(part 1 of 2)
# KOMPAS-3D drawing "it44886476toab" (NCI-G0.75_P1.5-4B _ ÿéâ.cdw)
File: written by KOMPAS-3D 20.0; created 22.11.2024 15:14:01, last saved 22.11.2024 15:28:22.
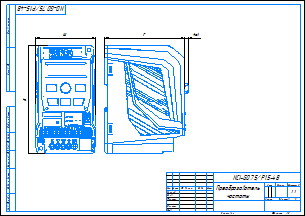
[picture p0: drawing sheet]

Sheet 1: A3, landscape

Document properties: Автор: admin

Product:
- Part/product: it44886476toab
    Масса: 2.32322
  - Body: Тело 2
      Масса: 0.00113358
  - Body: Тело 3
      Масса: 0.00113358
  - Body: Тело 4
      Масса: 0.000355433
  - Body: Тело 6
      Масса: 0.000355433
  - Body: Тело 7
      Масса: 0.000703761
  - Body: Тело 8
      Масса: 0.000703761
  - Body: Тело 10
      Масса: 0.0160396
  - Body: Тело 11
      Масса: 0.000703761
  - Body: Тело 13
      Масса: 0.000703761
  - Body: Тело 14
      Масса: 0.000703761
  - Body: Тело 18
      Масса: 0.0117014
  - Body: Тело 20
      Масса: 0.120334
  - Body: Тело 21
      Масса: 0.0864411
  - Body: Тело 22
      Масса: 0.0636504
  - Body: Тело 25
      Масса: 0.00135688
  - Body: Тело 26
      Масса: 0.00135688
  - Body: Тело 27
      Масса: 0.00135688
  - Body: Тело 30
      Масса: 0.000935996
  - Body: Тело 34
      Масса: 0.00831628
  - Body: Тело 36
      Масса: 0.0668131
  - Body: Тело 37
      Масса: 0.0343584
  - Body: Тело 39
      Масса: 0.0119524
  - Body: Тело 40
      Масса: 0.0119524
  - Body: Тело 42
      Масса: 0.0119524
  - Body: Тело 43
      Масса: 0.0119524
  - Body: Тело 46
      Масса: 0.0119034
  - Body: Тело 47
      Масса: 0.551587
  - Body: Тело 51
      Масса: 1.32696e-05
  - Body: Тело 54
      Масса: 1.32696e-05
  - Body: Тело 55
      Масса: 1.32696e-05
  - Body: Тело 56
      Масса: 1.32696e-05
  - Body: Тело 58
      Масса: 1.32696e-05
  - Body: Тело 61
      Масса: 1.32696e-05
  - Body: Тело 57
      Масса: 1.32696e-05
  - Body: Тело 63
      Масса: 1.65581e-05
  - Body: Тело 66
      Масса: 1.65581e-05
  - Body: Тело 67
      Масса: 1.65581e-05
  - Body: Тело 68
      Масса: 1.65581e-05
  - Body: Тело 69
      Масса: 1.65581e-05
  - Body: Тело 73
      Масса: 1.65581e-05
  - Body: Тело 48
      Масса: 0.00853877
  - Body: Тело 74
      Масса: 1.65581e-05
  - Body: Тело 78
      Масса: 1.65581e-05
  - Body: Тело 79
      Масса: 1.32696e-05
  - Body: Тело 80
      Масса: 1.32696e-05
  - Body: Тело 82
      Масса: 1.32696e-05
  - Body: Тело 83
      Масса: 1.32696e-05
  - Body: Тело 84
      Масса: 1.32696e-05
  - Body: Тело 87
      Масса: 0.000966482
  - Body: Тело 88
      Масса: 0.000873873
  - Body: Тело 15
      Масса: 0.000703761
  - Body: Тело 91
      Масса: 0.0246688
  - Body: Тело 92
      Масса: 3.83377e-05
  - Body: Тело 94
      Масса: 0.00554276
  - Body: Тело 96
      Масса: 0.00181049
  - Body: Тело 101
      Масса: 1.32696e-05
  - Body: Тело 90
      Масса: 0.000966482
  - Body: Тело 102
      Масса: 1.32696e-05
  - Body: Тело 104
      Масса: 1.32696e-05
  - Body: Тело 107
      Масса: 1.32696e-05
  - Body: Тело 108
      Масса: 1.32696e-05
  - Body: Тело 111
      Масса: 0.000194606
  - Body: Тело 115
      Масса: 0.000413213
  - Body: Тело 123
      Масса: 1.65581e-05
  - Body: Тело 127
      Масса: 1.32696e-05
  - Body: Тело 128
      Масса: 1.32696e-05
  - Body: Тело 129
      Масса: 1.32696e-05
  - Body: Тело 112
      Масса: 0.000413213
  - Body: Тело 130
      Масса: 1.32696e-05
  - Body: Тело 16
      Масса: 0.000703761
  - Body: Тело 131
      Масса: 1.32696e-05
  - Body: Тело 132
      Масса: 1.32696e-05
  - Body: Тело 133
      Масса: 1.32696e-05
  - Body: Тело 38
      Масса: 0.00631989
  - Body: Тело 135
      Масса: 1.32696e-05
  - Body: Тело 136
      Масса: 1.32696e-05
  - Body: Тело 142
      Масса: 0.000213463
  - Body: Тело 144
      Масса: 1.32696e-05
  - Body: Тело 62
      Масса: 1.32696e-05
  - Body: Тело 24
      Масса: 0.0110484
  - Body: Тело 147
      Масса: 1.32696e-05
  - Body: Тело 148
      Масса: 1.32696e-05
  - Body: Тело 154
      Масса: 1.32696e-05
  - Body: Тело 156
      Масса: 1.32696e-05
  - Body: Тело 158
      Масса: 1.32696e-05
  - Body: Тело 116
      Масса: 0.000413213
  - Body: Тело 159
      Масса: 1.32696e-05
  - Body: Тело 165
      Масса: 1.65581e-05
  - Body: Тело 166
      Масса: 1.32696e-05
  - Body: Тело 140
      Масса: 0.000213463
  - Body: Тело 169
      Масса: 1.32696e-05
  - Body: Тело 171
      Масса: 1.32696e-05
  - Body: Тело 153
      Масса: 1.32696e-05
  - Body: Тело 172
      Масса: 1.65581e-05
  - Body: Тело 173
      Масса: 1.32696e-05
  - Body: Тело 137
      Масса: 1.32696e-05
  - Body: Тело 45
      Масса: 0.0267013
  - Body: Тело 175
      Масса: 1.32696e-05
  - Body: Тело 177
      Масса: 1.32696e-05
  - Body: Тело 50
      Масса: 0.00101975
  - Body: Тело 44
      Масса: 0.0119524
  - Body: Тело 178
      Масса: 1.32696e-05
  - Body: Тело 179
      Масса: 1.32696e-05
  - Body: Тело 181
      Масса: 1.32696e-05
  - Body: Тело 182
      Масса: 1.32696e-05
  - Body: Тело 183
      Масса: 1.32696e-05
  - Body: Тело 188
      Масса: 1.32696e-05
  - Body: Тело 189
      Масса: 1.32696e-05
  - Body: Тело 192
      Масса: 1.32696e-05
  - Body: Тело 195
      Масса: 1.32696e-05
  - Body: Тело 197
      Масса: 1.32696e-05
  - Body: Тело 198
      Масса: 1.32696e-05
  - Body: Тело 199
      Масса: 1.32696e-05
  - Body: Тело 29
      Масса: 0.00135688
  - Body: Тело 201
      Масса: 1.32696e-05
  - Body: Тело 202
      Масса: 1.32696e-05
  - Body: Тело 205
      Масса: 1.32696e-05
  - Body: Тело 208
      Масса: 1.7366e-05
  - Body: Тело 209
      Масса: 1.32696e-05
  - Body: Тело 211
      Масса: 1.32696e-05
  - Body: Тело 212
      Масса: 1.32696e-05
  - Body: Тело 214
      Масса: 1.32696e-05
  - Body: Тело 9
      Масса: 0.000703761
  - Body: Тело 215
      Масса: 1.65581e-05
  - Body: Тело 217
      Масса: 1.32696e-05
  - Body: Тело 218
      Масса: 1.32696e-05
  - Body: Тело 219
      Масса: 1.32696e-05
  - Body: Тело 220
      Масса: 1.32696e-05
  - Body: Тело 221
      Масса: 1.65581e-05
  - Body: Тело 223
      Масса: 1.32696e-05
  - Body: Тело 162
      Масса: 1.65581e-05
  - Body: Тело 224
      Масса: 1.32696e-05
  - Body: Тело 228
      Масса: 1.32696e-05
  - Body: Тело 184
      Масса: 1.32696e-05
  - Body: Тело 230
      Масса: 1.32696e-05
  - Body: Тело 231
      Масса: 0.00398049
  - Body: Тело 232
      Масса: 5.48304e-05
  - Body: Тело 233
      Масса: 1.7366e-05
  - Body: Тело 1
      Масса: 0.00113358
  - Body: Тело 237
      Масса: 1.7366e-05
  - Body: Тело 141
      Масса: 0.000213463
  - Body: Тело 241
      Масса: 0.000424983
  - Body: Тело 65
      Масса: 1.65581e-05
  - Body: Тело 242
      Масса: 1.65581e-05
  - Body: Тело 243
      Масса: 1.65581e-05
  - Body: Тело 245
      Масса: 1.65581e-05
  - Body: Тело 234
      Масса: 1.7366e-05
  - Body: Тело 114
      Масса: 0.000413213
  - Body: Тело 19
      Масса: 0.0117014
  - Body: Тело 248
      Масса: 1.7366e-05
  - Body: Тело 249
      Масса: 1.7366e-05
  - Body: Тело 250
      Масса: 1.7366e-05
  - Body: Тело 254
      Масса: 1.32696e-05
  - Body: Тело 255
      Масса: 1.7366e-05
  - Body: Тело 119
      Масса: 0.000413213
  - Body: Тело 256
      Масса: 1.7366e-05
  - Body: Тело 167
      Масса: 1.32696e-05
  - Body: Тело 260
      Масса: 1.7366e-05
  - Body: Тело 261
      Масса: 3.83377e-05
  - Body: Тело 170
      Масса: 1.32696e-05
  - Body: Тело 463
      Масса: 0.000404362
  - Body: Тело 226
      Масса: 0.000413213
  - Body: Тело 464
      Масса: 0.00829425
  - Body: Тело 268
      Масса: 5.48304e-05
  - Body: Тело 467
      Масса: 0.00436982
  - Body: Тело 475
      Масса: 1.51773e-05
  - Body: Тело 451
      Масса: 6.34685e-05
  - Body: Тело 478
      Масса: 1.51773e-05
  - Body: Тело 465
      Масса: 0.00829114
  - Body: Тело 383
      Масса: 0.000340816
  - Body: Тело 125
      Масса: 1.65581e-05
  - Body: Тело 643
      Масса: 0.000158536
  - Body: Тело 514
      Масса: 1.51773e-05
  - Body: Тело 483
      Масса: 1.51773e-05
  - Body: Тело 486
      Масса: 0.000158536
  - Body: Тело 581
      Масса: 1.65581e-05
  - Body: Тело 490
      Масса: 1.51773e-05
  - Body: Тело 491
      Масса: 1.65581e-05
  - Body: Тело 433
      Масса: 0.000118347
  - Body: Тело 496
      Масса: 1.51773e-05
  - Body: Тело 437
      Масса: 0.00113358
  - Body: Тело 535
      Масса: 1.52051e-05
  - Body: Тело 498
      Масса: 1.51773e-05
  - Body: Тело 60
      Масса: 1.32696e-05
  - Body: Тело 369
      Масса: 1.32696e-05
  - Body: Тело 501
      Масса: 1.51773e-05
  - Body: Тело 503
      Масса: 1.51773e-05
  - Body: Тело 447
      Масса: 0.000307437
  - Body: Тело 187
      Масса: 1.32696e-05
  - Body: Тело 12
      Масса: 0.000703761
  - Body: Тело 507
      Масса: 1.51773e-05
  - Body: Тело 174
      Масса: 1.65581e-05
  - Body: Тело 587
      Масса: 1.32696e-05
  - Body: Тело 155
      Масса: 1.32696e-05
  - Body: Тело 512
      Масса: 1.51773e-05
  - Body: Тело 515
      Масса: 0.00507372
  - Body: Тело 510
      Масса: 1.51773e-05
  - Body: Тело 487
      Масса: 1.65581e-05
  - Body: Тело 432
      Масса: 0.000118347
  - Body: Тело 524
      Масса: 1.65581e-05
  - Body: Тело 637
      Масса: 1.51773e-05
  - Body: Тело 519
      Масса: 1.7366e-05
  - Body: Тело 427
      Масса: 1.32696e-05
  - Body: Тело 520
      Масса: 5.48304e-05
  - Body: Тело 326
      Масса: 1.32696e-05
  - Body: Тело 509
      Масса: 1.51773e-05
  - Body: Тело 571
      Масса: 0.00166679
  - Body: Тело 521
      Масса: 1.32696e-05
  - Body: Тело 522
      Масса: 1.65581e-05
  - Body: Тело 49
      Масса: 0.00944
  - Body: Тело 319
      Масса: 1.32696e-05
  - Body: Тело 458
      Масса: 1.51773e-05
  - Body: Тело 523
      Масса: 0.000255388
  - Body: Тело 191
      Масса: 1.32696e-05
  - Body: Тело 590
      Масса: 1.32696e-05
  - Body: Тело 599
      Масса: 7.12116e-06
  - Body: Тело 528
      Масса: 0.000141095
  - Body: Тело 64
      Масса: 1.65581e-05
  - Body: Тело 468
      Масса: 0.0253857
  - Body: Тело 216
      Масса: 0.000280294
  - Body: Тело 443
      Масса: 0.00113358
  - Body: Тело 239
      Масса: 5.48304e-05
  - Body: Тело 200
      Масса: 1.32696e-05
  - Body: Тело 579
      Масса: 0.00017125
  - Body: Тело 529
      Масса: 5.61948e-05
  - Body: Тело 493
      Масса: 1.51773e-05
  - Body: Тело 532
      Масса: 5.61948e-05
  - Body: Тело 343
      Масса: 0.00166679
  - Body: Тело 616
      Масса: 1.63919e-05
  - Body: Тело 462
      Масса: 0.000404362
  - Body: Тело 542
      Масса: 0.000158536
  - Body: Тело 543
      Масса: 0.000158536
  - Body: Тело 615
      Масса: 1.63919e-05
  - Body: Тело 149
      Масса: 1.32696e-05
  - Body: Тело 146
      Масса: 1.32696e-05
  - Body: Тело 469
      Масса: 0.0113891
  - Body: Тело 544
      Масса: 0.000158536
  - Body: Тело 295
      Масса: 1.65581e-05
  - Body: Тело 120
      Масса: 0.000413213
  - Body: Тело 352
      Масса: 2.90876e-05
  - Body: Тело 502
      Масса: 1.51773e-05
  - Body: Тело 461
      Масса: 0.000404362
  - Body: Тело 145
      Масса: 1.32696e-05
  - Body: Тело 545
      Масса: 1.51773e-05
  - Body: Тело 506
      Масса: 1.51773e-05
  - Body: Тело 71
      Масса: 1.65581e-05
  - Body: Тело 41
      Масса: 0.0119524
  - Body: Тело 547
      Масса: 0.000255388
  - Body: Тело 614
      Масса: 1.63919e-05
  - Body: Тело 257
      Масса: 1.7366e-05
  - Body: Тело 549
      Масса: 0.000255388
  - Body: Тело 204
      Масса: 1.32696e-05
  - Body: Тело 35
      Масса: 0.262997
  - Body: Тело 421
      Масса: 1.7366e-05
  - Body: Тело 258
      Масса: 1.7366e-05
  - Body: Тело 504
      Масса: 1.51773e-05
  - Body: Тело 366
      Масса: 1.7366e-05
  - Body: Тело 592
      Масса: 7.12116e-06
  - Body: Тело 32
      Масса: 0.0135217
  - Body: Тело 550
      Масса: 0.000255388
  - Body: Тело 157
      Масса: 1.32696e-05
  - Body: Тело 126
      Масса: 0.000512664
  - Body: Тело 314
      Масса: 1.7366e-05
  - Body: Тело 247
      Масса: 1.7366e-05
  - Body: Тело 23
      Масса: 0.0243258
  - Body: Тело 595
      Масса: 1.32696e-05
  - Body: Тело 534
      Масса: 1.32696e-05
  - Body: Тело 552
      Масса: 4.06595e-05
  - Body: Тело 176
      Масса: 1.32696e-05
  - Body: Тело 553
      Масса: 4.06595e-05
  - Body: Тело 28
      Масса: 0.00135688
  - Body: Тело 330
      Масса: 1.7366e-05
  - Body: Тело 190
      Масса: 1.32696e-05
  - Body: Тело 416
      Масса: 1.7366e-05
  - Body: Тело 435
      Масса: 0.00113358
  - Body: Тело 634
      Масса: 1.51773e-05
  - Body: Тело 555
      Масса: 0.00166679
  - Body: Тело 556
      Масса: 0.00166679
  - Body: Тело 602
      Масса: 5.61948e-05
  - Body: Тело 630
      Масса: 1.51773e-05
  - Body: Тело 558
      Масса: 0.00726683
  - Body: Тело 505
      Масса: 1.51773e-05
  - Body: Тело 500
      Масса: 1.51773e-05
  - Body: Тело 72
      Масса: 1.65581e-05
  - Body: Тело 279
      Масса: 1.32696e-05
  - Body: Тело 298
      Масса: 3.64495e-05
  - Body: Тело 168
      Масса: 1.32696e-05
  - Body: Тело 495
      Масса: 1.51773e-05
  - Body: Тело 336
      Масса: 3.64028e-05
  - Body: Тело 629
      Масса: 1.51773e-05
  - Body: Тело 263
      Масса: 1.7366e-05
  - Body: Тело 610
      Масса: 0.00166679
  - Body: Тело 609
      Масса: 1.7366e-05
  - Body: Тело 596
      Масса: 1.32696e-05
  - Body: Тело 538
      Масса: 1.51773e-05
  - Body: Тело 476
      Масса: 1.51773e-05
  - Body: Тело 227
      Масса: 1.32696e-05
  - Body: Тело 382
      Масса: 5.48304e-05
  - Body: Тело 470
      Масса: 0.00329329
  - Body: Тело 341
      Масса: 0.00166679
  - Body: Тело 426
      Масса: 1.32696e-05
  - Body: Тело 513
      Масса: 1.51773e-05
  - Body: Тело 236
      Масса: 1.7366e-05
  - Body: Тело 585
      Масса: 4.06595e-05
  - Body: Тело 649
      Масса: 0.00426189
  - Body: Тело 531
      Масса: 5.61948e-05
  - Body: Тело 627
      Масса: 0.000255388
  - Body: Тело 621
      Масса: 1.32696e-05
  - Body: Тело 349
      Масса: 1.7366e-05
  - Body: Тело 580
      Масса: 1.32696e-05
  - Body: Тело 631
      Масса: 1.51773e-05
  - Body: Тело 185
      Масса: 1.32696e-05
  - Body: Тело 117
      Масса: 0.000413213
  - Body: Тело 623
      Масса: 1.32696e-05
  - Body: Тело 605
      Масса: 5.61948e-05
  - Body: Тело 400
      Масса: 1.7366e-05
  - Body: Тело 139
      Масса: 0.000194606
  - Body: Тело 492
      Масса: 1.51773e-05
  - Body: Тело 612
      Масса: 0.000158536
  - Body: Тело 403
      Масса: 1.7366e-05
  - Body: Тело 460
      Масса: 3.90329e-05
  - Body: Тело 608
      Масса: 0.00166679
  - Body: Тело 635
      Масса: 1.65581e-05
  - Body: Тело 264
      Масса: 1.7366e-05
  - Body: Тело 646
      Масса: 0.000137594
  - Body: Тело 110
      Масса: 1.32696e-05
  - Body: Тело 302
      Масса: 1.65581e-05
  - Body: Тело 151
      Масса: 1.65581e-05
  - Body: Тело 497
      Масса: 1.51773e-05
  - Body: Тело 620
      Масса: 1.7366e-05
  - Body: Тело 518
      Масса: 0.00166679
  - Body: Тело 633
      Масса: 1.51773e-05
  - Body: Тело 564
      Масса: 4.06595e-05
  - Body: Тело 641
      Масса: 3.90329e-05
  - Body: Тело 494
      Масса: 1.51773e-05
  - Body: Тело 280
      Масса: 1.32696e-05
  - Body: Тело 81
      Масса: 1.32696e-05
  - Body: Тело 482
      Масса: 1.51773e-05
  - Body: Тело 594
      Масса: 1.32696e-05
  - Body: Тело 561
      Масса: 1.65581e-05
  - Body: Тело 253
      Масса: 1.7366e-05
  - Body: Тело 164
      Масса: 1.32696e-05
  - Body: Тело 525
      Масса: 0.000213463
  - Body: Тело 618
      Масса: 1.63919e-05
  - Body: Тело 642
      Масса: 3.90329e-05
  - Body: Тело 113
      Масса: 0.000413213
  - Body: Тело 546
      Масса: 0.000255388
  - Body: Тело 225
      Масса: 1.32696e-05
  - Body: Тело 138
      Масса: 2.23009e-05
  - Body: Тело 284
      Масса: 1.7366e-05
  - Body: Тело 485
      Масса: 0.000158536
  - Body: Тело 456
      Масса: 1.51773e-05
  - Body: Тело 489
      Масса: 1.51773e-05
  - Body: Тело 638
      Масса: 1.7366e-05
  - Body: Тело 563
      Масса: 4.06595e-05
  - Body: Тело 566
      Масса: 1.32696e-05
  - Body: Тело 160
      Масса: 1.32696e-05
  - Body: Тело 511
      Масса: 1.51773e-05
  - Body: Тело 541
      Масса: 0.000158536
  - Body: Тело 306
      Масса: 1.65581e-05
  - Body: Тело 356
      Масса: 1.65581e-05
  - Body: Тело 591
      Масса: 7.12116e-06
  - Body: Тело 313
      Масса: 1.7366e-05
  - Body: Тело 471
      Масса: 0.00329327
  - Body: Тело 289
      Масса: 1.7366e-05
  - Body: Тело 607
      Масса: 1.32696e-05
  - Body: Тело 603
      Масса: 5.61948e-05
  - Body: Тело 600
      Масса: 5.61948e-05
  - Body: Тело 121
      Масса: 0.000413213
  - Body: Тело 624
      Масса: 1.32696e-05
  - Body: Тело 527
      Масса: 0.000141095
  - Body: Тело 622
      Масса: 1.32696e-05
  - Body: Тело 484
      Масса: 0.000158536
  - Body: Тело 601
      Масса: 5.61948e-05
  - Body: Тело 296
      Масса: 3.6965e-05
  - Body: Тело 540
      Масса: 1.51773e-05
  - Body: Тело 210
      Масса: 1.32696e-05
  - Body: Тело 611
      Масса: 0.000158536
  - Body: Тело 161
      Масса: 1.32696e-05
  - Body: Тело 650
      Масса: 0.00426189
  - Body: Тело 604
      Масса: 5.61948e-05
  - Body: Тело 342
      Масса: 0.00166679
  - Body: Тело 251
      Масса: 1.7366e-05
  - Body: Тело 194
      Масса: 1.32696e-05
  - Body: Тело 568
      Масса: 1.32696e-05
  - Body: Тело 150
      Масса: 1.32696e-05
  - Body: Тело 640
      Масса: 1.63919e-05
  - Body: Тело 440
      Масса: 0.000355433
  - Body: Тело 499
      Масса: 1.51773e-05
  - Body: Тело 589
      Масса: 1.32696e-05
  - Body: Тело 361
      Масса: 1.32696e-05
  - Body: Тело 619
      Масса: 1.32696e-05
  - Body: Тело 405
      Масса: 1.32696e-05
  - Body: Тело 551
      Масса: 0.000255388
  - Body: Тело 598
      Масса: 7.12116e-06
  - Body: Тело 583
      Масса: 4.06595e-05
  - Body: Тело 411
      Масса: 5.48304e-05
  - Body: Тело 367
      Масса: 1.32696e-05
  - Body: Тело 488
      Масса: 1.51773e-05
  - Body: Тело 163
      Масса: 1.32696e-05
  - Body: Тело 109
      Масса: 1.32696e-05
  - Body: Тело 408
      Масса: 5.48304e-05
  - Body: Тело 593
      Масса: 1.32696e-05
  - Body: Тело 387
      Масса: 1.32696e-05
  - Body: Тело 613
      Масса: 1.63919e-05
  - Body: Тело 597
      Масса: 7.12116e-06
  - Body: Тело 118
      Масса: 0.000413213
  - Body: Тело 565
      Масса: 4.06595e-05
  - Body: Тело 632
      Масса: 1.51773e-05
  - Body: Тело 379
      Масса: 1.32696e-05
  - Body: Тело 562
      Масса: 0.000382752
  - Body: Тело 262
      Масса: 1.7366e-05
  - Body: Тело 586
      Масса: 1.32696e-05
  - Body: Тело 647
      Масса: 0.00426189
  - Body: Тело 533
      Масса: 5.61948e-05
  - Body: Тело 472
      Масса: 0.00329327
  - Body: Тело 409
      Масса: 5.48304e-05
  - Body: Тело 548
      Масса: 2.98222e-05
  - Body: Тело 474
      Масса: 1.51773e-05
  - Body: Тело 363
      Масса: 1.32696e-05
  - Body: Тело 276
      Масса: 1.7366e-05
  - Body: Тело 588
      Масса: 1.32696e-05
  - Body: Тело 70
      Масса: 1.65581e-05
  - Body: Тело 584
      Масса: 4.06595e-05
  - Body: Тело 644
      Масса: 0.000158536
  - Body: Тело 625
      Масса: 1.32696e-05
  - Body: Тело 213
      Масса: 1.32696e-05
  - Body: Тело 275
      Масса: 1.7366e-05
  - Body: Тело 320
      Масса: 1.32696e-05
  - Body: Тело 399
      Масса: 1.32696e-05
  - Body: Тело 574
      Масса: 4.06595e-05
  - Body: Тело 85
      Масса: 1.32696e-05
  - Body: Тело 576
      Масса: 1.32696e-05
  - Body: Тело 575
      Масса: 1.32696e-05
  - Body: Тело 376
      Масса: 1.32696e-05
  - Body: Тело 316
      Масса: 1.32696e-05
  - Body: Тело 449
      Масса: 0.0658364
  - Body: Тело 152
      Масса: 1.32696e-05
  - Body: Тело 559
      Масса: 1.65581e-05
  - Body: Тело 645
      Масса: 1.32696e-05
  - Body: Тело 207
      Масса: 1.32696e-05
  - Body: Тело 567
      Масса: 1.32696e-05
  - Body: Тело 572
      Масса: 1.32696e-05
  - Body: Тело 203
      Масса: 1.32696e-05
  - Body: Тело 582
      Масса: 1.65581e-05
  - Body: Тело 134
      Масса: 1.32696e-05
  - Body: Тело 626
      Масса: 1.32696e-05
  - Body: Тело 578
      Масса: 1.32696e-05
  - Body: Тело 569
      Масса: 1.32696e-05
  - Body: Тело 557
      Масса: 0.00166679
  - Body: Тело 459
      Масса: 3.90329e-05
  - Body: Тело 457
      Масса: 1.51773e-05
  - Body: Тело 539
      Масса: 1.51773e-05
  - Body: Тело 455
      Масса: 1.51773e-05
  - Body: Тело 428
      Масса: 0.146258
  - Body: Тело 454
      Масса: 0.000382752
  - Body: Тело 453
      Масса: 1.63919e-05
  - Body: Тело 417
      Масса: 1.32696e-05
  - Body: Тело 517
      Масса: 0.00106884
  - Body: Тело 418
      Масса: 1.7366e-05
  - Body: Тело 401
      Масса: 1.32696e-05
  - Body: Тело 53
      Масса: 1.32696e-05
  - Body: Тело 452
      Масса: 1.63919e-05
  - Body: Тело 315
      Масса: 1.7366e-05
  - Body: Тело 222
      Масса: 1.32696e-05
  - Body: Тело 450
      Масса: 6.34685e-05
  - Body: Тело 481
      Масса: 1.51773e-05
  - Body: Тело 448
      Масса: 0.000307437
  - Body: Тело 193
      Масса: 1.32696e-05
  - Body: Тело 392
      Масса: 1.32696e-05
  - Body: Тело 577
      Масса: 1.7366e-05
  - Body: Тело 508
      Масса: 1.51773e-05
  - Body: Тело 106
      Масса: 1.32696e-05
  - Body: Тело 438
      Масса: 0.000355433
  - Body: Тело 445
      Масса: 0.00113358
  - Body: Тело 246
      Масса: 1.65581e-05
  - Body: Тело 444
      Масса: 0.000355433
  - Body: Тело 554
      Масса: 4.06595e-05
  - Body: Тело 442
      Масса: 0.000355433
  - Body: Тело 441
      Масса: 0.00113358
  - Body: Тело 323
      Масса: 1.32696e-05
  - Body: Тело 606
      Масса: 0.000137594
  - Body: Тело 439
      Масса: 0.00113358
  - Body: Тело 436
      Масса: 0.000355433
  - Body: Тело 344
      Масса: 1.32696e-05
  - Body: Тело 124
      Масса: 1.65581e-05
  - Body: Тело 5
      Масса: 0.000355433
  - Body: Тело 434
      Масса: 0.000355433
  - Body: Тело 329
      Масса: 1.32696e-05
  - Body: Тело 364
      Масса: 1.32696e-05
  - Body: Тело 431
      Масса: 0.146258
  - Body: Тело 345
      Масса: 1.32696e-05
  - Body: Тело 350
      Масса: 1.7366e-05
  - Body: Тело 430
      Масса: 0.146258
  - Body: Тело 334
      Масса: 1.7366e-05
  - Body: Тело 429
      Масса: 0.146258
  - Body: Тело 206
      Масса: 1.32696e-05
  - Body: Тело 271
      Масса: 1.32696e-05
  - Body: Тело 365
      Масса: 1.32696e-05
  - Body: Тело 425
      Масса: 1.32696e-05
  - Body: Тело 305
      Масса: 1.65581e-05
  - Body: Тело 98
      Масса: 1.65581e-05
  - Body: Тело 424
      Масса: 1.7366e-05
  - Body: Тело 423
      Масса: 1.32696e-05
  - Body: Тело 381
      Масса: 1.7366e-05
  - Body: Тело 422
      Масса: 5.48304e-05
  - Body: Тело 186
      Масса: 1.32696e-05
  - Body: Тело 420
      Масса: 1.7366e-05
  - Body: Тело 648
      Масса: 0.00426189
  - Body: Тело 419
      Масса: 1.32696e-05
  - Body: Тело 235
      Масса: 1.7366e-05
  - Body: Тело 415
      Масса: 1.7366e-05
  - Body: Тело 537
      Масса: 0.000158536
  - Body: Тело 414
      Масса: 1.32696e-05
  - Body: Тело 413
      Масса: 1.32696e-05
  - Body: Тело 412
      Масса: 1.7366e-05
  - Body: Тело 636
      Масса: 1.65581e-05
  - Body: Тело 410
      Масса: 5.48304e-05
  - Body: Тело 97
      Масса: 0.0015961
  - Body: Тело 407
      Масса: 5.48304e-05
  - Body: Тело 52
      Масса: 1.32696e-05
  - Body: Тело 393
      Масса: 1.32696e-05
  - Body: Тело 406
      Масса: 1.65581e-05
  - Body: Тело 89
      Масса: 0.00142218
  - Body: Тело 404
      Масса: 1.32696e-05
  - Body: Тело 339
      Масса: 1.32696e-05
  - Body: Тело 59
      Масса: 1.32696e-05
  - Body: Тело 402
      Масса: 1.7366e-05
  - Body: Тело 479
      Масса: 1.51773e-05
  - Body: Тело 398
      Масса: 1.65581e-05
  - Body: Тело 397
      Масса: 1.32696e-05
  - Body: Тело 396
      Масса: 1.7366e-05
  - Body: Тело 354
      Масса: 0.000213463
  - Body: Тело 395
      Масса: 1.32696e-05
  - Body: Тело 394
      Масса: 1.32696e-05
  - Body: Тело 143
      Масса: 1.32696e-05
  - Body: Тело 390
      Масса: 1.65581e-05
  - Body: Тело 93
      Масса: 3.83377e-05
  - Body: Тело 389
      Масса: 1.65581e-05
  - Body: Тело 388
      Масса: 1.32696e-05
  - Body: Тело 229
      Масса: 1.32696e-05
  - Body: Тело 386
      Масса: 1.32696e-05
  - Body: Тело 291
      Масса: 0.000213463
  - Body: Тело 385
      Масса: 1.32696e-05
  - Body: Тело 639
      Масса: 1.63919e-05
  - Body: Тело 380
      Масса: 1.32696e-05
  - Body: Тело 322
      Масса: 1.32696e-05
  - Body: Тело 372
      Масса: 1.7366e-05
  - Body: Тело 95
      Масса: 0.000935996
  - Body: Тело 378
      Масса: 0.000413213
  - Body: Тело 259
      Масса: 1.7366e-05
  - Body: Тело 76
      Масса: 1.65581e-05
  - Body: Тело 351
      Масса: 2.90876e-05
  - Body: Тело 375
      Масса: 1.32696e-05
  - Body: Тело 373
      Масса: 1.32696e-05
  - Body: Тело 75
      Масса: 1.32696e-05
  - Body: Тело 371
      Масса: 1.7366e-05
  - Body: Тело 628
      Масса: 1.51773e-05
  - Body: Тело 333
      Масса: 1.32696e-05
  - Body: Тело 370
      Масса: 1.32696e-05
  - Body: Тело 368
      Масса: 1.32696e-05
  - Body: Тело 310
      Масса: 1.7366e-05
  - Body: Тело 86
      Масса: 1.32696e-05
  - Body: Тело 286
      Масса: 1.7366e-05
  - Body: Тело 359
      Масса: 1.7366e-05
  - Body: Тело 358
      Масса: 5.48304e-05
  - Body: Тело 466
      Масса: 0.00829114
  - Body: Тело 355
      Масса: 5.48304e-05
  - Body: Тело 353
      Масса: 1.7366e-05
  - Body: Тело 362
      Масса: 1.32696e-05
  - Body: Тело 281
      Масса: 1.32696e-05
  - Body: Тело 335
      Масса: 1.32696e-05
  - Body: Тело 346
      Масса: 1.32696e-05
  - Body: Тело 357
      Масса: 1.65581e-05
  - Body: Тело 196
      Масса: 1.32696e-05
  - Body: Тело 340
      Масса: 1.32696e-05
  - Body: Тело 570
      Масса: 4.06595e-05
  - Body: Тело 338
      Масса: 1.7366e-05
  - Body: Тело 337
      Масса: 1.7366e-05
  - Body: Тело 446
      Масса: 0.000307437
  - Body: Тело 332
      Масса: 1.7366e-05
  - Body: Тело 331
      Масса: 1.7366e-05
  - Body: Тело 301
      Масса: 1.65581e-05
  - Body: Тело 328
      Масса: 1.7366e-05
  - Body: Тело 105
      Масса: 1.32696e-05
  - Body: Тело 100
      Масса: 1.65581e-05
  - Body: Тело 31
      Масса: 0.0078835
  - Body: Тело 327
      Масса: 1.32696e-05
  - Body: Тело 617
      Масса: 1.63919e-05
  - Body: Тело 99
      Масса: 1.65581e-05
  - Body: Тело 325
      Масса: 1.32696e-05
  - Body: Тело 293
      Масса: 5.48304e-05
  - Body: Тело 288
      Масса: 1.7366e-05
  - Body: Тело 480
      Масса: 1.51773e-05
  - Body: Тело 324
      Масса: 1.32696e-05
  - Body: Тело 321
      Масса: 1.32696e-05
  - Body: Тело 318
      Масса: 1.32696e-05
  - Body: Тело 317
      Масса: 1.32696e-05
  - Body: Тело 312
      Масса: 5.48304e-05
  - Body: Тело 560
      Масса: 1.65581e-05
  - Body: Тело 122
      Масса: 1.65581e-05
  - Body: Тело 311
      Масса: 5.48304e-05
  - Body: Тело 473
      Масса: 0.00425494
  - Body: Тело 309
      Масса: 1.32696e-05
  - Body: Тело 240
      Масса: 1.7366e-05
  - Body: Тело 180
      Масса: 1.32696e-05
  - Body: Тело 308
      Масса: 0.000413213
  - Body: Тело 307
      Масса: 0.000213463
  - Body: Тело 304
      Масса: 1.65581e-05
  - Body: Тело 347
      Масса: 1.32696e-05
  - Body: Тело 360
      Масса: 1.32696e-05
  - Body: Тело 384
      Масса: 5.48304e-05
  - Body: Тело 516
      Масса: 0.00507377
  - Body: Тело 303
      Масса: 1.65581e-05
  - Body: Тело 300
      Масса: 1.65581e-05
  - Body: Тело 283
      Масса: 1.7366e-05
  - Body: Тело 299
      Масса: 3.64028e-05
  - Body: Тело 297
      Масса: 3.64631e-05
  - Body: Тело 294
      Масса: 0.000413213
  - Body: Тело 252
      Масса: 5.48304e-05
  - Body: Тело 33
      Масса: 0.00516019
  - Body: Тело 292
      Масса: 1.7366e-05
  - Body: Тело 269
      Масса: 5.48304e-05
  - Body: Тело 290
      Масса: 0.000413213
  - Body: Тело 287
      Масса: 1.32696e-05
  - Body: Тело 285
      Масса: 5.48304e-05
  - Body: Тело 391
      Масса: 1.32696e-05
  - Body: Тело 526
      Масса: 5.61948e-05
  - Body: Тело 477
      Масса: 1.51773e-05
  - Body: Тело 282
      Масса: 1.7366e-05
  - Body: Тело 278
      Масса: 1.7366e-05
  - Body: Тело 530
      Масса: 5.61948e-05
  - Body: Тело 277
      Масса: 1.7366e-05
  - Body: Тело 274
      Масса: 1.7366e-05
  - Body: Тело 238
      Масса: 1.7366e-05
  - Body: Тело 273
      Масса: 5.48304e-05
  - Body: Тело 272
      Масса: 1.7366e-05
  - Body: Тело 377
      Масса: 1.65581e-05
  - Body: Тело 536
      Масса: 0.000158536
  - Body: Тело 244
      Масса: 1.65581e-05
  - Body: Тело 77
      Масса: 1.32696e-05
  - Body: Тело 270
      Масса: 1.7366e-05
  - Body: Тело 348
      Масса: 1.32696e-05
  - Body: Тело 573
      Масса: 4.06595e-05
  - Body: Тело 103
      Масса: 1.32696e-05
  - Body: Тело 267
      Масса: 1.7366e-05
  - Body: Тело 266
      Масса: 1.7366e-05
  - Body: Тело 265
      Масса: 1.32696e-05
  - Body: Тело 374
      Масса: 5.48304e-05
  - Body: Тело 17
      Масса: 0.0117014

Title block, sheet 1: Наименование: Преобразователь / частоты; designation: NCI-G0.75/P1.5-4B; Количество листов документа: 1; Форматы листов документа: A3; stored path: P:\INSTART\Технический отдел\ОР\Прочие задачи\КД на номенклатурный ряд\КД на типоразмеры ПЧ\NCI\NCI-G0.75_P1.5-4B _ ШВГ.cdw

Referenced files in P:\INSTART\Технический отдел\ОР\Уралов\Проверка КД\: KD600M-4T2R2-20240807.m3d
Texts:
  Кривая без истории:10000
  Кривая без истории:10001
  Кривая без истории:10002
  Кривая без истории:10003
  Кривая без истории:10004
  Кривая без истории:10005
  Кривая без истории:10006
  Кривая без истории:10007
  Кривая без истории:10008
  Кривая без истории:10009
  Кривая без истории:10010
  Кривая без истории:10011
  Кривая без истории:10012
  Кривая без истории:10013
  Кривая без истории:10014
  Кривая без истории:10015
  Кривая без истории:10016
  Кривая без истории:10017
  Кривая без истории:10018
  Кривая без истории:10019
  Кривая без истории:10020
  Кривая без истории:10021
  Кривая без истории:10022
  Кривая без истории:10023
  Кривая без истории:10024
  Кривая без истории:10025
  Кривая без истории:10026
  Кривая без истории:10027
  Кривая без истории:10028
  Кривая без истории:10029
  Кривая без истории:10030
  Кривая без истории:10031
  Кривая без истории:10032
  Кривая без истории:10033
  Кривая без истории:10034
  Кривая без истории:10035
  Кривая без истории:10036
  Кривая без истории:10037
  Кривая без истории:10038
  Кривая без истории:10039
  Кривая без истории:10040
  Кривая без истории:10041
  Кривая без истории:10042
  Кривая без истории:10043
  Кривая без истории:10044
  Кривая без истории:10045
  Кривая без истории:10046
  Кривая без истории:10047
  Кривая без истории:10048
  Кривая без истории:10049
  Кривая без истории:10050
  Кривая без истории:10051
  Кривая без истории:10052
  Кривая без истории:10053
  Кривая без истории:10054
  Кривая без истории:10055
  Кривая без истории:10056
  Кривая без истории:10057
  Кривая без истории:10058
  Кривая без истории:10059
  Кривая без истории:10060
  Кривая без истории:10061
  Кривая без истории:10062
  Кривая без истории:10063
  Кривая без истории:10064
  Кривая без истории:10065
  Кривая без истории:10066
  Кривая без истории:10067
  Кривая без истории:10068
  Кривая без истории:10069
  Кривая без истории:10070
  Кривая без истории:10071
  Кривая без истории:10072
  Кривая без истории:10073
  Кривая без истории:10074
  Кривая без истории:10075
  Кривая без истории:10076
  Кривая без истории:10077
  Кривая без истории:10078
  Кривая без истории:10079
  Кривая без истории:10080
  Кривая без истории:10081
  Кривая без истории:10082
  Кривая без истории:10083
  Кривая без истории:10084
  Кривая без истории:10085
  Кривая без истории:10086
  Кривая без истории:10087
  Кривая без истории:10088
  Кривая без истории:10089
  Кривая без истории:10090
  Кривая без истории:10091
  Кривая без истории:10092
  Кривая без истории:10093
  Кривая без истории:10094
  Кривая без истории:10095
  Кривая без истории:10096
  Кривая без истории:10097
  Кривая без истории:10098
  Кривая без истории:10099
  Кривая без истории:10100
  Кривая без истории:10101
  Кривая без истории:10102
  Кривая без истории:10103
  Кривая без истории:10104
  Кривая без истории:10105
  Кривая без истории:10106
  Кривая без истории:10107
  Кривая без истории:10108
  Кривая без истории:10109
  Кривая без истории:10110
  Кривая без истории:10111
  Кривая без истории:10112
  Кривая без истории:10113
  Кривая без истории:10114
  Кривая без истории:10115
  Кривая без истории:10116
  Кривая без истории:10117
  Кривая без истории:10118
  Кривая без истории:10119
  Кривая без истории:10120
  Кривая без истории:10121
  Кривая без истории:10122
  Кривая без истории:10123
  Кривая без истории:10124
  Кривая без истории:10125
  Кривая без истории:10126
  Кривая без истории:10127
  Кривая без истории:10128
  Кривая без истории:10129
  Кривая без истории:10130
  Кривая без истории:10131
  Кривая без истории:10132
  Кривая без истории:10133
  Кривая без истории:10134
  Кривая без истории:10135
  Кривая без истории:10136
  Кривая без истории:10137
  Кривая без истории:10138
  Кривая без истории:10139
  Кривая без истории:10140
  Кривая без истории:10141
  Кривая без истории:10142
  Кривая без истории:10143
  Кривая без истории:10144
  Кривая без истории:10145
  Кривая без истории:10146
  Кривая без истории:10147
  Кривая без истории:10148
  Кривая без истории:10149
  Кривая без истории:10150
  Кривая без истории:10151
  Кривая без истории:10152
  Кривая без истории:10153
  Кривая без истории:10154
  Кривая без истории:10155
  Кривая без истории:10156
  Кривая без истории:10157
  Кривая без истории:10158
  Кривая без истории:10159
  Кривая без истории:10160
  Кривая без истории:10161
  Кривая без истории:10162
  Кривая без истории:10163
  Кривая без истории:10164
  Кривая без истории:10165
  Кривая без истории:10166
  Кривая без истории:10167
  Кривая без истории:10168
  Кривая без истории:10169
  Кривая без истории:10170
  Кривая без истории:10171
  Кривая без истории:10172
  Кривая без истории:10173
  Кривая без истории:10174
  Кривая без истории:10175
  Кривая без истории:10176
  Кривая без истории:10177
  Кривая без истории:10178
  Кривая без истории:10179
  Кривая без истории:10180
  Кривая без истории:10181
  Кривая без истории:10182
  Кривая без истории:10183
  Кривая без истории:10184
  Кривая без истории:10185
  Кривая без истории:10186
  Кривая без истории:10187
  Кривая без истории:10188
  Кривая без истории:10189
  Кривая без истории:10190
  Кривая без истории:10191
  Кривая без истории:10192
  Кривая без истории:10193
  Кривая без истории:10194
  Кривая без истории:10195
  Кривая без истории:10196
  Кривая без истории:10197
  Кривая без истории:10198
  Кривая без истории:10199
  Кривая без истории:10200
  Кривая без истории:10201
  Кривая без истории:10202
  Кривая без истории:10203
  Кривая без истории:10204
  Кривая без истории:10205
  Кривая без истории:10206
  Кривая без истории:10207
  Кривая без истории:10208
  Кривая без истории:10209
  Кривая без истории:10210
  Кривая без истории:10211
  Кривая без истории:10212
  Кривая без истории:10213
  Кривая без истории:10214
  Кривая без истории:10215
  Кривая без истории:10216
  Кривая без истории:10217
  Кривая без истории:10218
  Кривая без истории:10219
  Кривая без истории:10220
  Кривая без истории:10221
  Кривая без истории:10222
  Кривая без истории:10223
  Кривая без истории:10224
  Кривая без истории:10225
  Кривая без истории:10226
  Кривая без истории:10227
  Кривая без истории:10228
  Кривая без истории:10229
  Кривая без истории:10230
  Кривая без истории:10231
  Кривая без истории:10232
  Кривая без истории:10233
  Кривая без истории:10234
  Кривая без истории:10235
  Кривая без истории:10236
  Кривая без истории:10237
  Кривая без истории:10238
  Кривая без истории:10239
  Кривая без истории:10240
  Кривая без истории:10241
  Кривая без истории:10242
  Кривая без истории:10243
  Кривая без истории:10244
  Кривая без истории:10245
  Кривая без истории:10246
  Кривая без истории:10247
  Кривая без истории:10248
  Кривая без истории:10249
  Кривая без истории:10250
  Кривая без истории:10251
  Кривая без истории:10252
  Кривая без истории:10253
  Кривая без истории:10254
  Кривая без истории:10255
  Кривая без истории:10256
  Кривая без истории:10257
  Кривая без истории:10258
  Кривая без истории:10259
  Кривая без истории:10260
  Кривая без истории:10261
  Кривая без истории:10262
  Кривая без истории:10263
  Кривая без истории:10264
  Кривая без истории:10265
  Кривая без истории:10266
  Кривая без истории:10267
  Кривая без истории:10268
  Кривая без истории:10269
  Кривая без истории:10270
  Кривая без истории:10271
  Кривая без истории:10272
  Кривая без истории:10273
  Кривая без истории:10274
  Кривая без истории:10275
  Кривая без истории:10276
  Кривая без истории:10277
  Кривая без истории:10278
  Кривая без истории:10279
  Кривая без истории:10280
  Кривая без истории:10281
  Кривая без истории:10282
  Кривая без истории:10283
  Кривая без истории:10284
  Кривая без истории:10285
  Кривая без истории:10286
  Кривая без истории:10287
  Кривая без истории:10288
  Кривая без истории:10289
  Кривая без истории:10290
  Кривая без истории:10291
  Кривая без истории:10292
  Кривая без истории:10293
  Кривая без истории:10294
  Кривая без истории:10295
  Кривая без истории:10296
  Кривая без истории:10297
  Кривая без истории:10298
  Кривая без истории:10299
  Кривая без истории:10300
  Кривая без истории:10301
  Кривая без истории:10302
  Кривая без истории:10303
  Кривая без истории:10304
  Кривая без истории:10305
  Кривая без истории:10306
  Кривая без истории:10307
  Кривая без истории:10308
  Кривая без истории:10309
  Кривая без истории:10310
  Кривая без истории:10311
  Кривая без истории:10312
  Кривая без истории:10313
  Кривая без истории:10314
  Кривая без истории:10315
  Кривая без истории:10316
  Кривая без истории:10317
  Кривая без истории:10318
  Кривая без истории:10319
  Кривая без истории:10320
  Кривая без истории:10321
  Кривая без истории:10322
  Кривая без истории:10323
  Кривая без истории:10324
  Кривая без истории:10325
  Кривая без истории:10326
  Кривая без истории:10327
  Кривая без истории:10328
  Кривая без истории:10329
  Кривая без истории:10330
  Кривая без истории:10331
  Кривая без истории:10332
  Кривая без истории:10333
  Кривая без истории:10334
  Кривая без истории:10335
  Кривая без истории:10336
  Кривая без истории:10337
  Кривая без истории:10338
  Кривая без истории:10339
  Кривая без истории:10340
  Кривая без истории:10341
  Кривая без истории:10342
  Кривая без истории:10343
  Кривая без истории:10344
  Кривая без истории:10345
  Кривая без истории:10346
  Кривая без истории:10347
  Кривая без истории:10348
  Кривая без истории:10349
  Кривая без истории:10350
  Кривая без истории:10351
  Кривая без истории:10352
  Кривая без истории:10353
  Кривая без истории:10354
  Кривая без истории:10355
  Кривая без истории:10356
  Кривая без истории:10357
  Кривая без истории:10358
  Кривая без истории:10359
  Кривая без истории:10360
  Кривая без истории:10361
  Кривая без истории:10362
  Кривая без истории:10363
  Кривая без истории:10364
  Кривая без истории:10365
  Кривая без истории:10366
  Кривая без истории:10367
  Кривая без истории:10368
  Кривая без истории:10369
  Кривая без истории:10370
  Кривая без истории:10371
  Кривая без истории:10372
  Кривая без истории:10373
  Кривая без истории:10374
  Кривая без истории:10375
  Кривая без истории:10376
  Кривая без истории:10377
  Кривая без истории:10378
  Кривая без истории:10379
  Кривая без истории:10380
  Кривая без истории:10381
  Кривая без истории:10382
  Кривая без истории:10383
  Кривая без истории:10384
  Кривая без истории:10385
  Кривая без истории:10386
  Кривая без истории:10387
  Кривая без истории:10388
  Кривая без истории:10389
  Кривая без истории:10390
  Кривая без истории:10391
  Кривая без истории:10392
  Кривая без истории:10393
  Кривая без истории:10394
  Кривая без истории:10395
  Кривая без истории:10396
  Кривая без истории:10397
  Кривая без истории:10398
  Кривая без истории:10399
  Кривая без истории:10400
  Кривая без истории:10401
  Кривая без истории:10402
  Кривая без истории:10403
  Кривая без истории:10404
  Кривая без истории:10405
  Кривая без истории:10406
  Кривая без истории:10407
  Кривая без истории:10408
  Кривая без истории:10409
  Кривая без истории:10410
  Кривая без истории:10411
  Кривая без истории:10412
  Кривая без истории:10413
  Кривая без истории:10414
  Кривая без истории:10415
  Кривая без истории:10416
  Кривая без истории:10417
  Кривая без истории:10418
  Кривая без истории:10419
  Кривая без истории:10420
  Кривая без истории:10421
  Кривая без истории:10422
  Кривая без истории:10423
  Кривая без истории:10424
  Кривая без истории:10425
  Кривая без истории:10426
  Кривая без истории:10427
  Кривая без истории:10428
  Кривая без истории:10429
  Кривая без истории:10430
  Кривая без истории:10431
  Кривая без истории:10432
  Кривая без истории:10433
  Кривая без истории:10434
  Кривая без истории:10435
  Кривая без истории:10436
  Кривая без истории:10437
  Кривая без истории:10438
  Кривая без истории:10439
  Кривая без истории:10440
  Кривая без истории:10441
  Кривая без истории:10442
  Кривая без истории:10443
  Кривая без истории:10444
  Кривая без истории:10445
  Кривая без истории:10446
  Кривая без истории:10447
  Кривая без истории:10448
  Кривая без истории:10449
  Кривая без истории:10450
  Кривая без истории:10451
  Кривая без истории:10452
  Кривая без истории:10453
  Кривая без истории:10454
  Кривая без истории:10455
  Кривая без истории:10456
  Кривая без истории:10457
  Кривая без истории:10458
  Кривая без истории:10459
  Кривая без истории:10460
  Кривая без истории:10461
  Кривая без истории:10462
  Кривая без истории:10463
  Кривая без истории:10464
  Кривая без истории:10465
  Кривая без истории:10466
  Кривая без истории:10467
  Кривая без истории:10468
  Кривая без истории:10469
  Кривая без истории:10470
  Кривая без истории:10471
  Кривая без истории:10472
  Кривая без истории:10473
  Кривая без истории:10474
  Кривая без истории:10475
  Кривая без истории:10476
  Кривая без истории:10477
  Кривая без истории:10478
  Кривая без истории:10479
  Кривая без истории:10480
  Кривая без истории:10481
  Кривая без истории:10482
  Кривая без истории:10483
  Кривая без истории:10484
  Кривая без истории:10485
  Кривая без истории:10486
  Кривая без истории:10487
  Кривая без истории:10488
  Кривая без истории:10489
  Кривая без истории:10490
  Кривая без истории:10491
  Кривая без истории:10492
  Кривая без истории:10493
  Кривая без истории:10494
  Кривая без истории:10495
  Кривая без истории:10496
  Кривая без истории:10497
  Кривая без истории:10498
  Кривая без истории:10499
  Кривая без истории:10500
  Кривая без истории:10501
  Кривая без истории:10502
  Кривая без истории:10503
  Кривая без истории:10504
  Кривая без истории:10505
  Кривая без истории:10506
  Кривая без истории:10507
  Кривая без истории:10508
  Кривая без истории:10509
  Кривая без истории:10510
  Кривая без истории:10511
  Кривая без истории:10512
  Кривая без истории:10513
  Кривая без истории:10514
  Кривая без истории:10515
  Кривая без истории:10516
  Кривая без истории:10517
  Кривая без истории:10518
  Кривая без истории:10519
  Кривая без истории:10520
  Кривая без истории:10521
  Кривая без истории:10522
  Кривая без истории:10523
  Кривая без истории:10524
  Кривая без истории:10525
  Кривая без истории:10526
  Кривая без истории:10527
  Кривая без истории:10528
  Кривая без истории:10529
  Кривая без истории:10530
  Кривая без истории:10531
  Кривая без истории:10532
  Кривая без истории:10533
  Кривая без истории:10534
  Кривая без истории:10535
  Кривая без истории:10536
  Кривая без истории:10537
  Кривая без истории:10538
  Кривая без истории:10539
  Кривая без истории:10540
  Кривая без истории:10541
  Кривая без истории:10542
  Кривая без истории:10543
  Кривая без истории:10544
  Кривая без истории:10545
  Кривая без истории:10546
  Кривая без истории:10547
  Кривая без истории:10548
  Кривая без истории:10549
  Кривая без истории:10550
  Кривая без истории:10551
  Кривая без истории:10552
  Кривая без истории:10553
  Кривая без истории:10554
  Кривая без истории:10555
  Кривая без истории:10556
  Кривая без истории:10557
  Кривая без истории:10558
  Кривая без истории:10559
  Кривая без истории:10560
  Кривая без истории:10561
  Кривая без истории:10562
  Кривая без истории:10563
  Кривая без истории:10564
  Кривая без истории:10565
  Кривая без истории:10566
  Кривая без истории:10567
  Кривая без истории:10568
  Кривая без истории:10569
  Кривая без истории:10570
  Кривая без истории:10571
  Кривая без истории:10572
  Кривая без истории:10573
  Кривая без истории:10574
  Кривая без истории:10575
  Кривая без истории:10576
  Кривая без истории:10577
  Кривая без истории:10578
  Кривая без истории:10579
  Кривая без истории:10580
  Кривая без истории:10581
  Кривая без истории:10582
  Кривая без истории:10583
  Кривая без истории:10584
  Кривая без истории:10585
  Кривая без истории:10586
  Кривая без истории:10587
  Кривая без истории:10588
  Кривая без истории:10589
  Кривая без истории:10590
  Кривая без истории:10591
  Кривая без истории:10592
  Кривая без истории:10593
  Кривая без истории:10594
  Кривая без истории:10595
  Кривая без истории:10596
  Кривая без истории:10597
  Кривая без истории:10598
  Кривая без истории:10599
  Кривая без истории:10600
  Кривая без истории:10601
  Кривая без истории:10602
  Кривая без истории:10603
  Кривая без истории:10604
  Кривая без истории:10605
  Кривая без истории:10606
  Кривая без истории:10607
  Кривая без истории:10608
  Кривая без истории:10609
  Кривая без истории:10610
  Кривая без истории:10611
  Кривая без истории:10612
  Кривая без истории:10613
  Кривая без истории:10614
  Кривая без истории:10615
  Кривая без истории:10616
  Кривая без истории:10617
  Кривая без истории:10618
  Кривая без истории:10619
  Кривая без истории:10620
  Кривая без истории:10621
  Кривая без истории:10622
  Кривая без истории:10623
  Кривая без истории:10624
  Кривая без истории:10625
  Кривая без истории:10626
  Кривая без истории:10627
  Кривая без истории:10628
  Кривая без истории:10629
  Кривая без истории:10630
  Кривая без истории:10631
  Кривая без истории:10632
  Кривая без истории:10633
  Кривая без истории:10634
  Кривая без истории:10635
  Кривая без истории:10636
  Кривая без истории:10637
  Кривая без истории:10638
  Кривая без истории:10639
  Кривая без истории:10640
  Кривая без истории:10641
  Кривая без истории:10642
  Кривая без истории:10643
  Кривая без истории:10644
  Кривая без истории:10645
  Кривая без истории:10646
  Кривая без истории:10647
  Кривая без истории:10648
  Кривая без истории:10649
  Кривая без истории:10650
  Кривая без истории:10651
  Кривая без истории:10652
  Кривая без истории:10653
  Кривая без истории:10654
  Кривая без истории:10655
  Кривая без истории:10656
  Кривая без истории:10657
  Кривая без истории:10658
  Кривая без истории:10659
  Кривая без истории:10660
  Кривая без истории:10661
  Кривая без истории:10662
  Кривая без истории:10663
  Кривая без истории:10664
  Кривая без истории:10665
  Кривая без истории:10666
  Кривая без истории:10667
  Кривая без истории:10668
  Кривая без истории:10669
  Кривая без истории:10670
  Кривая без истории:10671
  Кривая без истории:10672
  Кривая без истории:10673
  Кривая без истории:10674
  Кривая без истории:10675
  Кривая без истории:10676
  Кривая без истории:10677
  Кривая без истории:10678
  Кривая без истории:10679
  Кривая без истории:10680
  Кривая без истории:10681
  Кривая без истории:10682
  Кривая без истории:10683
  Кривая без истории:10684
  Кривая без истории:10685
  Кривая без истории:10686
  Кривая без истории:10687
  Кривая без истории:10688
  Кривая без истории:10689
  Кривая без истории:10690
  Кривая без истории:10691
  Кривая без истории:10692
  Кривая без истории:10693
  Кривая без истории:10694
  Кривая без истории:10695
  Кривая без истории:10696
  Кривая без истории:10697
  Кривая без истории:10698
  Кривая без истории:10699
  Кривая без истории:10700
  Кривая без истории:10701
  Кривая без истории:10702
  Кривая без истории:10703
  Кривая без истории:10704
  Кривая без истории:10705
  Кривая без истории:10706
  Кривая без истории:10707
  Кривая без истории:10708
  Кривая без истории:10709
  Кривая без истории:10710
  Кривая без истории:10711
  Кривая без истории:10712
  Кривая без истории:10713
  Кривая без истории:10714
  Кривая без истории:10715
  Кривая без истории:10716
  Кривая без истории:10717
  Кривая без истории:10718
  Кривая без истории:10719
  Кривая без истории:10720
  Кривая без истории:10721
  Кривая без истории:10722
  Кривая без истории:10723
  Кривая без истории:10724
  Кривая без истории:10725
  Кривая без истории:10726
  Кривая без истории:10727
  Кривая без истории:10728
  Кривая без истории:10729
  Кривая без истории:10730
  Кривая без истории:10731
  Кривая без истории:10732
  Кривая без истории:10733
  Кривая без истории:10734
  Кривая без истории:10735
  Кривая без истории:10736
  Кривая без истории:10737
  Кривая без истории:10738
  Кривая без истории:10739
  Кривая без истории:10740
  Кривая без истории:10741
  Кривая без истории:10742
  Кривая без истории:10743
  Кривая без истории:10744
  Кривая без истории:10745
  Кривая без истории:10746
  Кривая без истории:10747
  Кривая без истории:10748
  Кривая без истории:10749
  Кривая без истории:10750
  Кривая без истории:10751
  Кривая без истории:10752
  Кривая без истории:10753
  Кривая без истории:10754
  Кривая без истории:10755
  Кривая без истории:10756
  Кривая без истории:10757
  Кривая без истории:10758
  Кривая без истории:10759
  Кривая без истории:10760
  Кривая без истории:10761
  Кривая без истории:10762
  Кривая без истории:10763
  Кривая без истории:10764
  Кривая без истории:10765
  Кривая без истории:10766
  Кривая без истории:10767
  Кривая без истории:10768
  Кривая без истории:10769
  Кривая без истории:10770
  Кривая без истории:10771
  Кривая без истории:10772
